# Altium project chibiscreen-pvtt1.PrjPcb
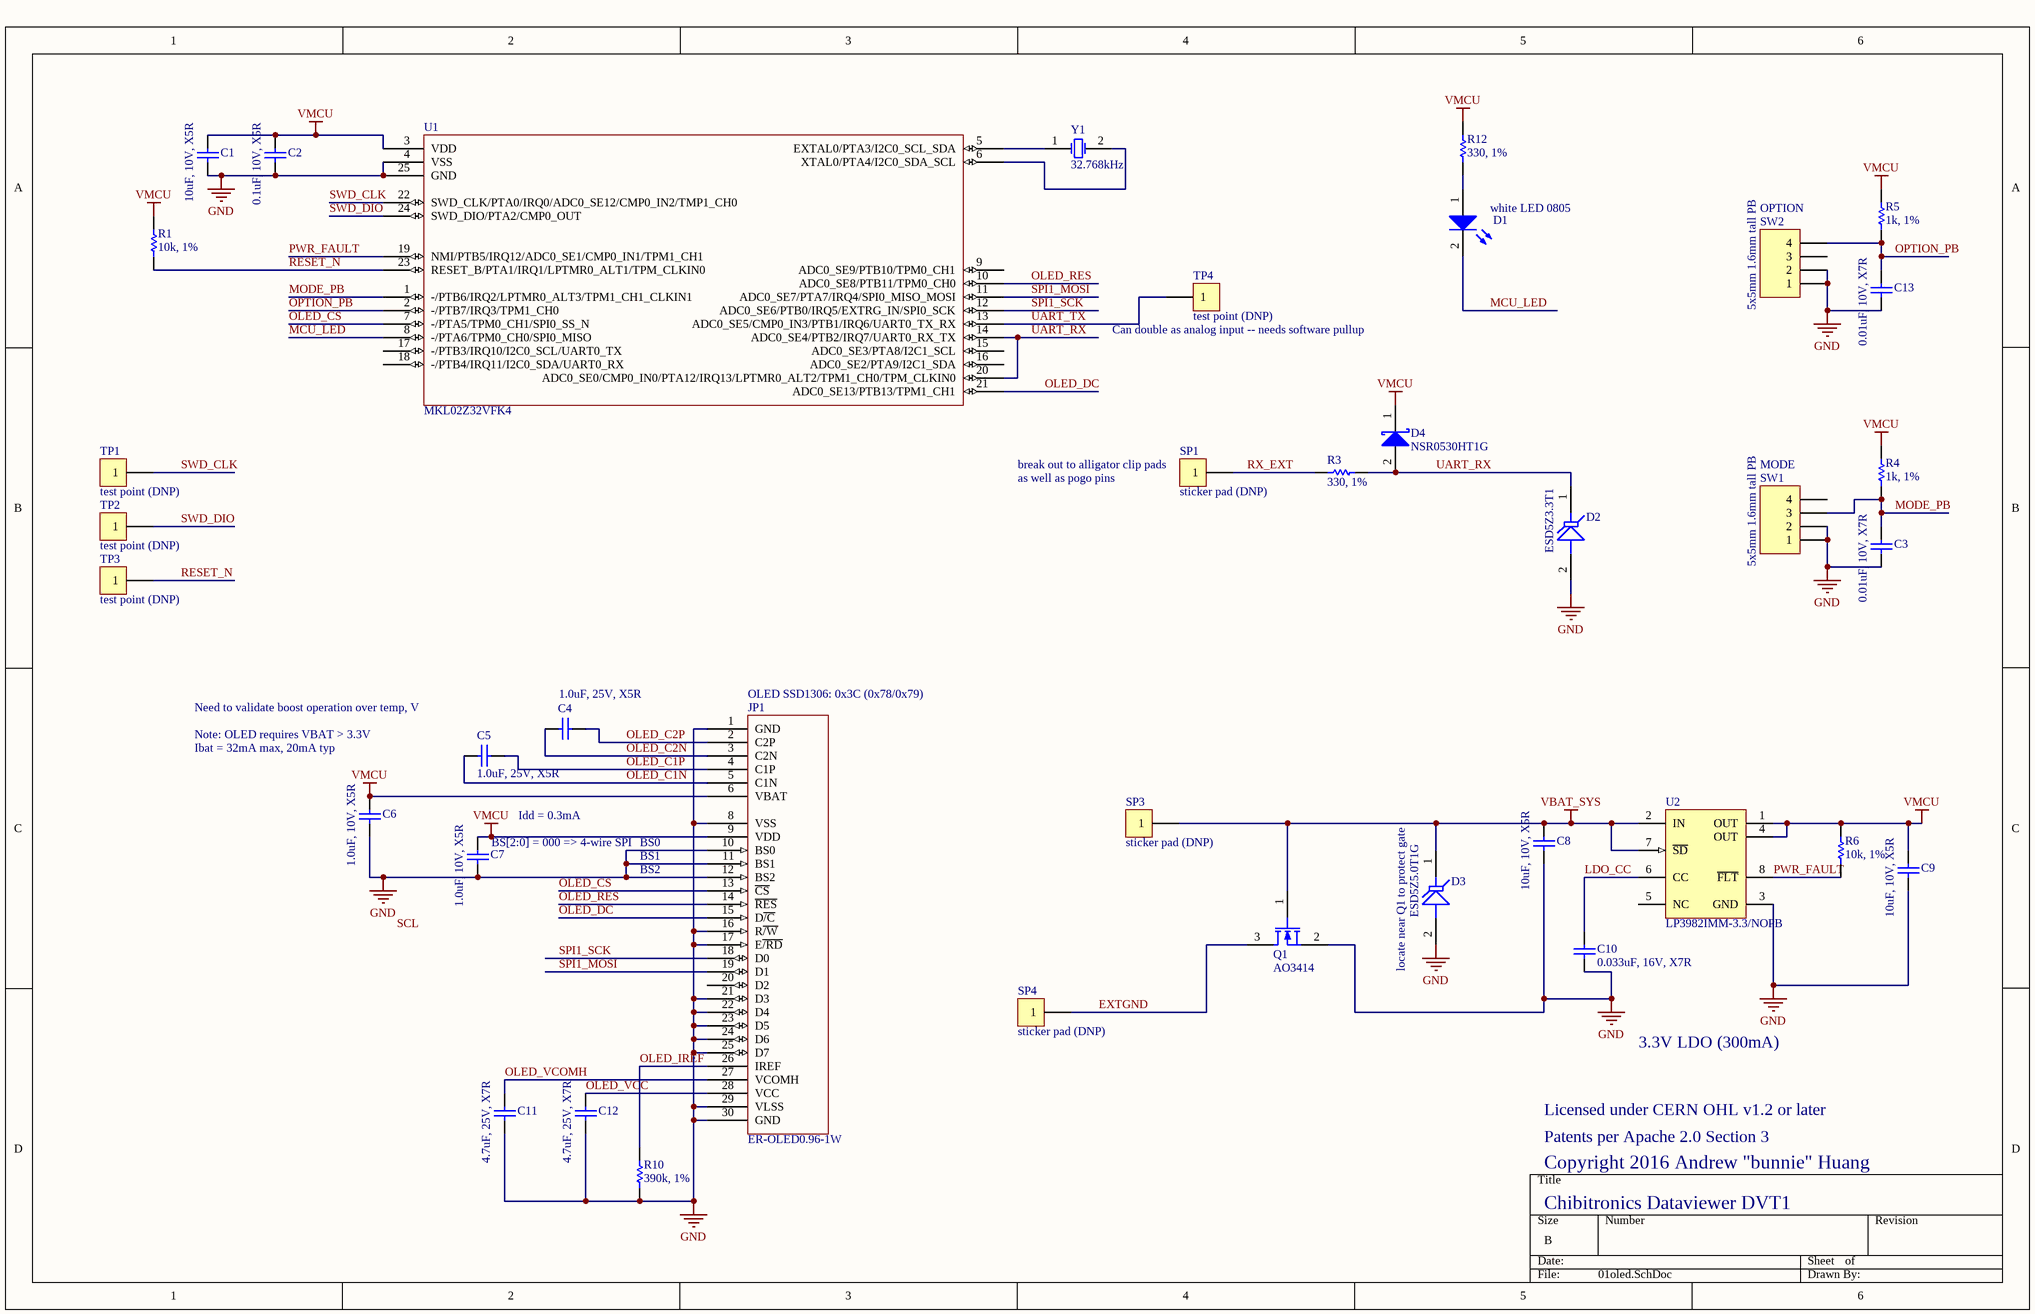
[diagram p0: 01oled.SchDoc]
1 sheet, 38 parts. Net scope: global (net labels, ports and power ports of the same name join across sheets).
Board file: chibiscreen-pvt1d.PcbDoc

## Sheet 01oled.SchDoc
size B

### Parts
C1  10uF, 10V, X5R  [CAPC2012N]
C2  0.1uF, 10V, X5R  [CAPC1005N]
C3  0.01uF, 10V, X7R  [CAPC1005N]
C4  1.0uF, 25V, X5R  [CAPC1608N]
C5  1.0uF, 25V, X5R  [CAPC1608N]
C6  1.0uF, 10V, X5R  [CAPC1005N]
C7  1.0uF, 10V, X5R  [CAPC1005N]
C8  10uF, 10V, X5R  [CAPC2012N]
C9  10uF, 10V, X5R  [CAPC2012N]
C10  0.033uF, 16V, X7R  [CAPC1005N]
C11  4.7uF, 25V, X7R  [CAPC2012N]
C12  4.7uF, 25V, X7R  [CAPC2012N]
C13  0.01uF, 10V, X7R  [CAPC1005N]
D1  white LED 0805  [CD2012-0805]
D2  ESD5Z3.3T1  [SOD-523]
D3  ESD5Z5.0T1G  [SOD-523]
D4  NSR0530HT1G  [SOD-323]
JP1  ER-OLED0.96-1W  [ER-OLED0.96-FOLD]
Q1  AO3414  [SOT23-3N]
R1  10k, 1%  [RESC1005N]
R3  330, 1%  [RESC1005N]
R4  1k, 1%  [RESC1005N]
R5  1k, 1%  [RESC1005N]
R6  10k, 1%  [RESC1005N]
R10  390k, 1%  [RESC1005N]
R12  330, 1%  [RESC1005N]
SP1  sticker pad (DNP)  [TP_SMT_38mil]
SP3  sticker pad (DNP)  [TP_SMT_38mil]
SP4  sticker pad (DNP)  [TP_SMT_38mil]
SW1  5x5mm 1.6mm tall PB  [SWITCH_TS-1187A]
SW2  5x5mm 1.6mm tall PB  [SWITCH_TS-1187A]
TP1  test point (DNP)  [TP_2MM_SQ]
TP2  test point (DNP)  [TP_2MM_SQ]
TP3  test point (DNP)  [TP_2MM_SQ]
TP4  test point (DNP)  [TP_2MM_SQ]
U1  MKL02Z32VFK4  [QFN50P400X400X100_HS-25N]
U2  LP3982IMM-3.3/NOPB  [MUA08A_N]
Y1  32.768kHz  [ABS07-120]

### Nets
GND: C1.2 C2.2 C3.2 C6.2 C7.2 C8.2 C9.2 C10.1 C11.2 C12.2 C13.2 D2.2(A) D3.2(A) JP1.1(GND) JP1.8(VSS) JP1.10(BS0) JP1.11(BS1) JP1.12(BS2) JP1.16(R~{/W}) JP1.17(E~{/RD}) JP1.21(D3) JP1.22(D4) JP1.23(D5) JP1.24(D6) JP1.25(D7) JP1.29(VLSS) JP1.30(GND) Q1.2(S) R10.2 SW1.1 SW1.2 SW2.1 SW2.2 U1.4(VSS) U1.25(GND) U2.3(GND)
VBAT_SYS: C8.1 D3.1(K) Q1.1(G) SP3.1 U2.2(IN) U2.7(~{SD})
VMCU: C1.1 C2.1 C6.1 C7.1 C9.1 D4.1(K) JP1.6(VBAT) JP1.9(VDD) R1.1 R4.1 R5.1 R6.1 R12.1 U1.3(VDD) U2.1(OUT) U2.4(OUT)
EXTGND: Q1.3(D) SP4.1
LDO_CC: C10.2 U2.6(CC)
MCU_LED: D1.2(K) U1.8(-/PTA6/TPM0_CH0/SPI0_MISO)
MODE_PB: C3.1 R4.2 SW1.3 U1.1(-/PTB6/IRQ2/LPTMR0_ALT3/TPM1_CH1_CLKIN1)
OLED_C1N: C5.1 JP1.5(C1N)
OLED_C1P: C5.2 JP1.4(C1P)
OLED_C2N: C4.1 JP1.3(C2N)
OLED_C2P: C4.2 JP1.2(C2P)
OLED_CS: JP1.13(~{CS}) U1.7(-/PTA5/TPM0_CH1/SPI0_SS_N)
OLED_DC: JP1.15(D~{/C}) U1.21(ADC0_SE13/PTB13/TPM1_CH1)
OLED_IREF: JP1.26(IREF) R10.1
OLED_RES: JP1.14(~{RES}) U1.10(ADC0_SE8/PTB11/TPM0_CH0)
OLED_VCC: C12.1 JP1.28(VCC)
OLED_VCOMH: C11.1 JP1.27(VCOMH)
OPTION_PB: C13.1 R5.2 SW2.4 U1.2(-/PTB7/IRQ3/TPM1_CH0)
PWR_FAULT: R6.2 U1.19(NMI/PTB5/IRQ12/ADC0_SE1/CMP0_IN1/TPM1_CH1) U2.8(~{FLT})
RESET_N: R1.2 TP3.1 U1.23(RESET_B/PTA1/IRQ1/LPTMR0_ALT1/TPM_CLKIN0)
RX_EXT: R3.1 SP1.1
SPI1_MOSI: JP1.19(D1) U1.11(ADC0_SE7/PTA7/IRQ4/SPI0_MISO_MOSI)
SPI1_SCK: JP1.18(D0) U1.12(ADC0_SE6/PTB0/IRQ5/EXTRG_IN/SPI0_SCK)
SWD_CLK: TP1.1 U1.22(SWD_CLK/PTA0/IRQ0/ADC0_SE12/CMP0_IN2/TMP1_CH0)
SWD_DIO: TP2.1 U1.24(SWD_DIO/PTA2/CMP0_OUT)
UART_RX: D2.1(K) D4.2(A) R3.2 U1.14(ADC0_SE4/PTB2/IRQ7/UART0_RX_TX) U1.20(ADC0_SE0/CMP0_IN0/PTA12/IRQ13/LPTMR0_ALT2/TPM1_CH0/TPM_CLKIN0)
UART_TX: TP4.1 U1.13(ADC0_SE5/CMP0_IN3/PTB1/IRQ6/UART0_TX_RX)
NetD1_1: D1.1(A) R12.2
NetU1_5: U1.5(EXTAL0/PTA3/I2C0_SCL_SDA) Y1.1(OSC1)
NetU1_6: U1.6(XTAL0/PTA4/I2C0_SDA_SCL) Y1.2(OSC2)

Not connected (* = marked no-connect by the designer): JP1 20(D2); SW1 4; SW2 3; U1 9(ADC0_SE9/PTB10/TPM0_CH1) 15(ADC0_SE3/PTA8/I2C1_SCL) 16(ADC0_SE2/PTA9/I2C1_SDA) 17(-/PTB3/IRQ10/I2C0_SCL/UART0_TX) 18(-/PTB4/IRQ11/I2C0_SDA/UART0_RX); U2 5(NC)

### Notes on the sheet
- (near SW2) OPTION
- (near TP4) Can double as analog input -- needs software pullup
- (near SP1) break out to alligator clip pads
- as well as pogo pins
- (near SW1) MODE
- (near C5) Need to validate boost operation over temp, V
- (near JP1) OLED SSD1306: 0x3C (0x78/0x79)
- Note: OLED requires VBAT > 3.3V
- Ibat = 32mA max, 20mA typ
- (near C7) BS[2:0] = 000 => 4-wire SPI
- Idd = 0.3mA
- BS0
- BS1
- BS2
- (near D3) locate near Q1 to protect gate
- 3.3V LDO (300mA)
- Licensed under CERN OHL v1.2 or later
- Copyright 2016 Andrew "bunnie" Huang
- Patents per Apache 2.0 Section 3
- Chibitronics Dataviewer DVT1
- Labels drawn without touching a wire or pin: SCL

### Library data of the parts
C1 C8 C9 = Cap Semi: Capacitor (Semiconductor SIM Model); MPN: CL21A106KPCLQNC; VENDOR: Samsung; MYPN: C-106-10-X5R-0805
C2 = Cap Semi: Capacitor (Semiconductor SIM Model); MPN: CL05A104KP5NNNC; VENDOR: Samsung; MYPN: C-104-10-X5R-0402
C3 C13 = Cap Semi: Capacitor (Semiconductor SIM Model); MPN: CL05B103KP5NNNC; VENDOR: Samsung; MYPN: C-103-10-X7R-0402
C4 C5 = Cap Semi: Capacitor (Semiconductor SIM Model); MPN: CL10A105KA8NNNC; VENDOR: Samsung; MYPN: C-105-25-X5R-0603
C6 C7 = Cap Semi: Capacitor (Semiconductor SIM Model); MPN: CL05A105KP5NNND; VENDOR: Samsung; MYPN: C-105-10-X5R-0402
C10 = Cap Semi: Capacitor (Semiconductor SIM Model); MPN: CL05B333KO5NNNC; VENDOR: Samsung; MYPN: C-333-16-X7R-0402
C11 C12 = Cap Semi: Capacitor (Semiconductor SIM Model); MPN: CL21B475KAFNNNE; VENDOR: Samsung; MYPN: C-475-25-X7R-0805
D1 = LED2: White LED; MPN: CB-2012QWC-P8; MYPN: D-LED-WHITE-0805; VENDOR: Cheng Guang Xing
D2 = Tranzorb: On Semi 3.3V standoff TVS diode; MPN: ESD5Z3.3T1G; VENDOR: On Semiconductor; MYPN: D-ESD5Z3.3T1
D3 = Tranzorb: On Semi 5.0V standoff TVS diode; VENDOR: On Semiconductor; MYPN: D-ESD5Z5.0T1G
D4 = D Schottky: Schottky Diode; MPN: NSR0530H-D; VENDOR: Semtech HK LTD; MYPN: D-S-0p5-30-0p37-SOD323
JP1 = ER-OLED0.96-3W: 0.96in OLED, 128x64, white; VENDOR: EastRising; MYPN: JP-ER-OLED0.96-1W
Q1 = MOSFET-N: N-Channel MOSFET; VENDOR: Alpha & Omega Semiconductor; MYPN: Q-AO3414
R1 R6 = Res1: Resistor; MPN: RS02U103FT; VENDOR: Fenghua; MYPN: R-103-1P-1_16W-0402
R3 = Res1: Resistor; MPN: RS02U331FT; VENDOR: Fenghua; MYPN: R-101-1P-1_16W-0402
R4 R5 = Res1: Resistor; MPN: RS02U102FT; VENDOR: Fenghua; MYPN: R-102-1P-1_16W-0402
R10 = Res1: Resistor; MPN: RS02U394FT; VENDOR: Fenghua; MYPN: R-394-1P-1_16W-0402
R12 = Res1: Resistor; MPN: RS02U331FT; VENDOR: Fenghua; MYPN: R-331-1P-1_16W-0402
SP1 SP3 SP4 TP1-TP4 = CON1: Connector
SW1 SW2 = Header 4: Chi Fung TS-1187A; MPN: SW-PB-5X5-1.6; VENDOR: Kangdeli
U1 = MKL02Z32VFK4: Kinetis KL02 32 KB Flash, 48MHz Cortex-M0+; MYPN: UMKL02Z32VFK4; VENDOR: NXP
U2 = LP3982IMM-3.3/NOPB: Micropower, Ultra Low-Dropout, Low-Noise, 300mA CMOS Regulator, 8-pin Mini SOIC, Pb-Free; Manufacturer: National Semiconductor; PackageTopMarking: ZXTT*LEUB; PowerWise: N; CompType: LDO IC; High-Reliability: Y; MYPN: ULP3982IMM-3.3/NOPB; VENDOR: TI
Y1 = XTAL: 3.2 x 1.5mm 32.768 kHz crystal, 6pF CL 70k ESR, 20ppm; MPN: SJFC1332K06F20; VENDOR: Songji; MYPN: X-32.768K-SONGJI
